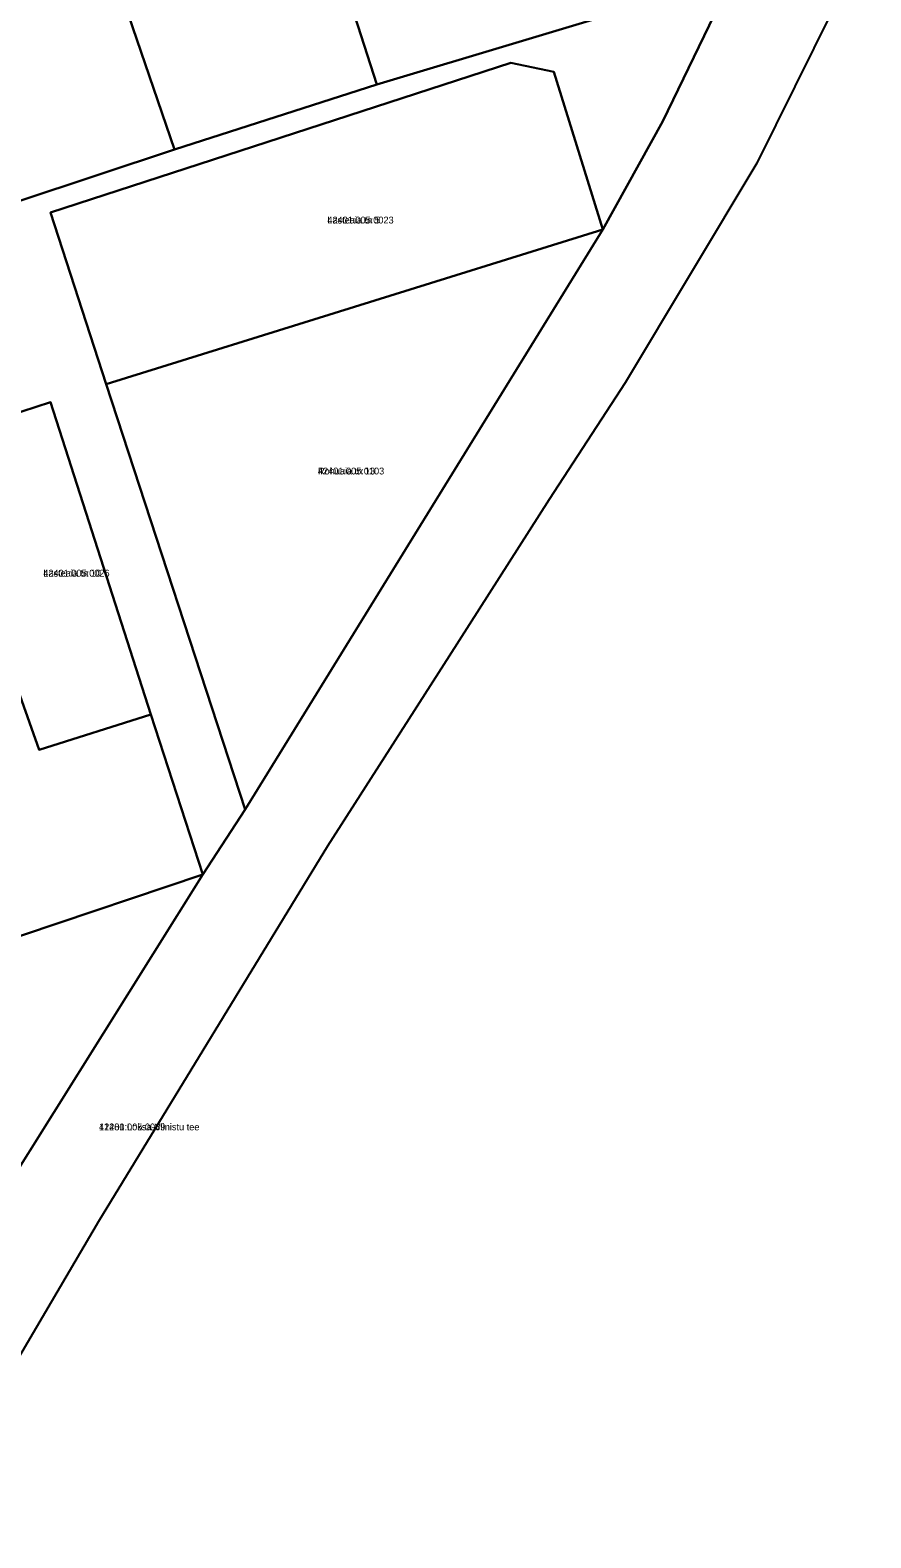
# Model space of a CAD drawing. Extents: x 595979 to 597983, y 6604231 to 6607350.
# Drawn here: x 597714.5 to 597898.3, y 6606228.5 to 6606558.1 of the extents above; entities that cross this region are included whole.
import ezdxf

# ---------------------------------------------------------------- set-up
doc = ezdxf.new("R2010")
doc.units = 0
for name, color, linetype in [('L_AADRESS', 7, 'Continuous'), ('PIIR', 7, 'Continuous'), ('TUNNUS', 7, 'Continuous')]:
    doc.layers.add(name, color=color, linetype=linetype)

msp = doc.modelspace()

# ---------------------------------------------------------------- linework, layer by layer
at = {"layer": 'PIIR'}
for points in [[(597762.54, 6606632.31), (597793.92, 6606642.25), (597831.54, 6606619.92), (597871.24, 6606596.51), (597853.26, 6606565.17), (597790.29, 6606546.25)], [(597716.73, 6606617.61), (597762.54, 6606632.31), (597790.29, 6606546.25), (597746.05, 6606532.03)], [(597682.91, 6606606.97), (597716.73, 6606617.61), (597746.05, 6606532.03), (597711.99, 6606520.69)], [(597718.87, 6606518.22), (597819.57, 6606550.94), (597829.01, 6606548.98), (597839.67, 6606514.5), (597731.05, 6606480.73)], [(597731.05, 6606480.73), (597839.67, 6606514.5), (597761.45, 6606387.69)], [(597693.79, 6606468.64), (597718.88, 6606476.75), (597740.87, 6606408.48), (597716.44, 6606400.74), (597710.55, 6606417.45)], [(597617.16, 6606369.13), (597655.54, 6606381.43), (597649.74, 6606397.94), (597710.55, 6606417.45), (597716.44, 6606400.74), (597740.87, 6606408.48), (597752.2, 6606373.52), (597633.81, 6606333.73), (597622.49, 6606350.88)], [(597633.81, 6606333.73), (597752.2, 6606373.52), (597686.96, 6606269.47), (597659.89, 6606298.14)]]:
    msp.add_lwpolyline(points, close=True, dxfattribs=at)
for points in [[(597565.06, 6606039.67), (597587.91, 6606081.73), (597610.46, 6606123.21), (597617.1, 6606136.22), (597670.49, 6606242.36), (597684.7, 6606264.98), (597686.96, 6606269.47), (597752.2, 6606373.52), (597761.45, 6606387.69), (597839.67, 6606514.5), (597852.82, 6606538.23), (597878.8, 6606591.86)], [(597878.8, 6606591.86), (597852.82, 6606538.23), (597839.67, 6606514.5), (597829.01, 6606548.98), (597819.57, 6606550.94), (597718.87, 6606518.22), (597731.05, 6606480.73), (597761.45, 6606387.69), (597752.2, 6606373.52), (597740.87, 6606408.48), (597718.88, 6606476.75), (597693.79, 6606468.64)], [(597898.31, 6606579.37), (597873.37, 6606529.02), (597844.57, 6606480.97), (597827.98, 6606455.52), (597806.07, 6606421.26), (597786.61, 6606390.85), (597779.47, 6606379.69), (597729.41, 6606297.64), (597695.07, 6606239.29), (597655.09, 6606168.29), (597622.28, 6606110.03), (597610.7, 6606083.09), (597599, 6606056.25), (597583.97, 6606026)], [(597405, 6606315.04), (597432.66, 6606344.54), (597479.92, 6606388.47), (597555.81, 6606443.42), (597561.36, 6606446.55), (597585.97, 6606440.29), (597598.71, 6606445.03), (597591.35, 6606467.02), (597568.32, 6606535.1), (597575.11, 6606537.67), (597604.59, 6606449.84), (597712.18, 6606485.07), (597701.21, 6606517.72), (597711.99, 6606520.69), (597746.05, 6606532.03), (597790.29, 6606546.25), (597853.26, 6606565.17)]]:
    msp.add_lwpolyline(points, dxfattribs=at)

# ---------------------------------------------------------------- texts
at = {"layer": 'L_AADRESS'}
for s, p in [('Lasteaia tn 5', (597779.45, 6606515.84)), ('Rohuaia tn 13', (597777.39, 6606460.97)), ('Lasteaia tn 10', (597717.33, 6606438.64)), ('11280 Loksa-Viinistu tee', (597729.51, 6606317.57))]:
    msp.add_text(s, height=1.5, dxfattribs=at).set_placement(p)
at = {"layer": 'TUNNUS'}
for s, p in [('42401:005:0023', (597779.45, 6606515.84)), ('42401:005:0103', (597777.39, 6606460.97)), ('42401:005:0026', (597717.33, 6606438.64)), ('42401:005:0069', (597729.51, 6606317.57))]:
    msp.add_text(s, height=1.5, dxfattribs=at).set_placement(p)

doc.saveas('drawing.dxf')
